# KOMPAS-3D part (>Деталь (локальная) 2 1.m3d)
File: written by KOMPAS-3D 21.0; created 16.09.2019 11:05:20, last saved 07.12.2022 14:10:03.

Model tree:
1. Эскиз:1  (with: Элемент выдавливания:1)
2. Элемент выдавливания:1
     Расстояние 1 = 10
3. Эскиз:2  (with: Элемент выдавливания:1)
4. Элемент выдавливания:2
     Расстояние 2 = 10
5. Эскиз:3  (with: Элемент выдавливания:1)
6. Элемент выдавливания:3
     Расстояние 2 = 10

Referenced files in C:\PDM_TEST\Проекты МО\71.17 ОНПЗ\81.47.00.000 М-266\81.47.00.500 Питатель вибрац\: Сборка.a3d
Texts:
  Штрихпунктирная 2 ум 4
  Штрихпунктирная 2 ум 2
  Штрихпунктирная 2
  Штриховая ум 4
  Штриховая ум 2
  Осевая ув 2
  Осевая ум 4
  Осевая ум 2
